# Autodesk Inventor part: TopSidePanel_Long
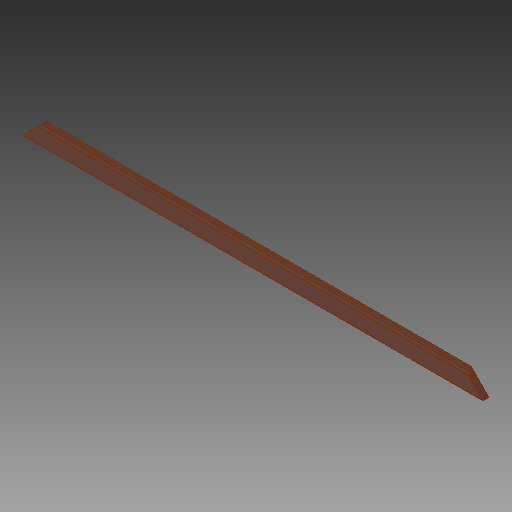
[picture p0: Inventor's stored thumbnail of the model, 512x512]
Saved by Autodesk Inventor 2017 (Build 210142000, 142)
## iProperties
Created: 2017-05
Part Number: TopSidePanel_Long
Material: Generic
Document SubType Name: Modeling
Designer: Savy
Density: 1 g/cm^3
Appearance: Default
Mass: 401.967 g
Surface Area: 992.081 cm^2
Volume: 401.967 cm^3
Author: Savy
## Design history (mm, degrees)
feature "SOLID1"
body "Solid1"
